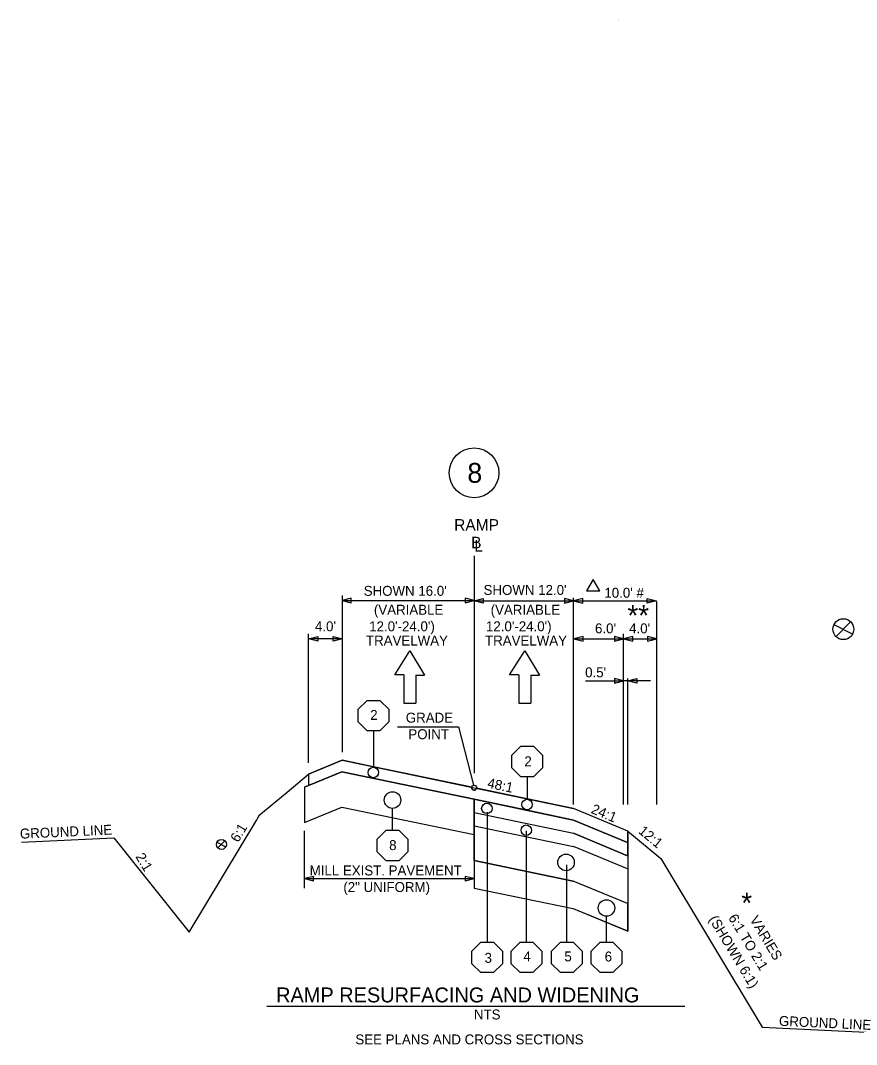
# Model space of a CAD drawing. Extents: x 5017 to 5774, y 4942 to 5266.
# Drawn here: x 5028.4 to 5129.3, y 5142.5 to 5266.1 of the extents above; entities that cross this region are included whole.
import ezdxf

# ---------------------------------------------------------------- set-up
doc = ezdxf.new("R2010")
doc.units = 0
for name, color, linetype in [('Level 2', 7, 'Continuous'), ('Level 20', 7, 'Continuous'), ('Level 25', 7, 'Continuous'), ('RD_DDB_EX_Tx', 7, 'Continuous'), ('RD_QTY_Intermediate', 7, 'Continuous'), ('RD_QTY_Surf_Course', 7, 'Continuous'), ('RD_SHT_Typical', 7, 'Continuous'), ('RD_TX_TypSect', 7, 'Continuous'), ('RD_XS_ExGround', 7, 'Continuous'), ('RD_XS_ExPaveRet', 7, 'Continuous'), ('typical_on', 7, 'Continuous')]:
    doc.layers.add(name, color=color, linetype=linetype)

msp = doc.modelspace()

# ---------------------------------------------------------------- linework, layer by layer
at = {"layer": 'Level 2'}
for p, q in [((5100.63, 5266.14), (5100.63, 5266.14)), ((5100.63, 5266.08), (5100.63, 5266.08))]:
    msp.add_line(p, q, dxfattribs=at)
at = {"layer": 'Level 20'}
for p, q in [((5073.55, 5187.12), (5075.37, 5190.03)), ((5075.37, 5190.03), (5077.16, 5187.11)), ((5087.43, 5187.12), (5089.25, 5190.03)), ((5089.25, 5190.03), (5091.04, 5187.11)), ((5074.64, 5187.12), (5073.55, 5187.12)), ((5074.64, 5187.12), (5074.64, 5183.72)), ((5076.1, 5187.11), (5077.16, 5187.11)), ((5076.1, 5187.11), (5076.1, 5183.71)), ((5088.52, 5187.12), (5087.43, 5187.12)), ((5088.52, 5187.12), (5088.52, 5183.72)), ((5089.98, 5187.11), (5091.04, 5187.11)), ((5089.98, 5187.11), (5089.98, 5183.71)), ((5074.64, 5183.72), (5076.1, 5183.71)), ((5088.52, 5183.72), (5089.98, 5183.71))]:
    msp.add_line(p, q, dxfattribs=at)
at = {"layer": 'Level 25'}
msp.add_lwpolyline([(5073.9, 5180.87), (5081.26, 5180.87), (5083.07, 5173.79)], dxfattribs=at)
msp.add_circle((5083.13, 5211.52), 3, dxfattribs=at)
at = {"layer": 'RD_DDB_EX_Tx'}
for p, q in [((5095.12, 5162.23), (5083.15, 5164.73)), ((5101.66, 5159.51), (5095.12, 5162.23)), ((5083.15, 5161.39), (5095.12, 5158.9)), ((5095.12, 5158.9), (5101.69, 5156.17)), ((5101.69, 5156.17), (5101.69, 5159.51))]:
    msp.add_line(p, q, dxfattribs=at)
for points in [[(5083.15, 5164.73), (5083.15, 5162.52), (5083.15, 5161.39)], [(5101.69, 5159.51), (5101.66, 5159.51)]]:
    msp.add_lwpolyline(points, dxfattribs=at)
msp.add_circle((5099.12, 5158.98), 1, dxfattribs=at)
at = {"layer": 'RD_QTY_Intermediate'}
for p, q in [((5083.15, 5172.1), (5083.15, 5170.51)), ((5083.15, 5170.51), (5095.15, 5168.01)), ((5101.67, 5166.89), (5095.15, 5169.6)), ((5095.15, 5168.01), (5101.67, 5165.29)), ((5101.69, 5165.29), (5101.69, 5166.89))]:
    msp.add_line(p, q, dxfattribs=at)
for points in [[(5095.15, 5169.6), (5089.51, 5170.78), (5083.15, 5172.1)], [(5101.69, 5166.89), (5101.67, 5166.89)], [(5101.67, 5165.29), (5101.69, 5165.29)]]:
    msp.add_lwpolyline(points, dxfattribs=at)
at = {"layer": 'RD_QTY_Surf_Course'}
for p, q in [((5067.21, 5176.82), (5063.16, 5175.13)), ((5070.99, 5176.03), (5067.21, 5176.82)), ((5070.99, 5175.97), (5070.99, 5176.03)), ((5082.85, 5173.56), (5071.01, 5176.03)), ((5063.16, 5173.76), (5067.18, 5175.43)), ((5063.16, 5175.13), (5063.16, 5173.76)), ((5067.18, 5175.43), (5083.15, 5172.1)), ((5089.55, 5172.17), (5083.44, 5173.44)), ((5083.15, 5172.1), (5095.15, 5169.6)), ((5089.55, 5172.1), (5089.55, 5172.17)), ((5095.15, 5171), (5089.56, 5172.16)), ((5101.69, 5168.27), (5095.15, 5171)), ((5095.15, 5169.6), (5101.67, 5166.89)), ((5101.69, 5166.89), (5101.69, 5168.27))]:
    msp.add_line(p, q, dxfattribs=at)
for points in [[(5071.01, 5176.03), (5070.99, 5175.97)], [(5089.56, 5172.16), (5089.55, 5172.1)], [(5101.67, 5166.89), (5101.69, 5166.89)]]:
    msp.add_lwpolyline(points, dxfattribs=at)
for centre in [(5070.97, 5175.34), (5089.54, 5171.47)]:
    msp.add_circle(centre, 0.63, dxfattribs=at)
msp.add_arc((5083.15, 5173.5), 0.3, 168.2319, 348.2319, dxfattribs=at)
at = {"layer": 'RD_SHT_Typical'}
for p, q in [((5063.16, 5175.13), (5067.21, 5176.82)), ((5062.66, 5173.55), (5067.18, 5175.43)), ((5063.16, 5173.76), (5067.18, 5175.43)), ((5063.16, 5175.13), (5063.16, 5173.76)), ((5062.66, 5173.55), (5062.66, 5169.29)), ((5083.15, 5172.1), (5083.15, 5170.73)), ((5062.66, 5169.29), (5067.18, 5171.17)), ((5083.15, 5170.73), (5083.15, 5167.84)), ((5101.69, 5168.27), (5095.15, 5171)), ((5101.67, 5166.89), (5095.15, 5169.6)), ((5083.15, 5164.73), (5083.15, 5168.91)), ((5101.69, 5168.27), (5105.69, 5164.94)), ((5101.69, 5168.27), (5101.69, 5156.17)), ((5101.67, 5165.29), (5095.15, 5168.01)), ((5101.67, 5163.69), (5095.15, 5166.41)), ((5105.69, 5164.94), (5117.91, 5144.57)), ((5101.66, 5159.51), (5095.12, 5162.23)), ((5101.69, 5156.17), (5095.15, 5158.89))]:
    msp.add_line(p, q, dxfattribs=at)
for points in [[(5067.21, 5176.82), (5083.15, 5173.5)], [(5067.18, 5175.43), (5083.15, 5172.1)], [(5067.18, 5175.43), (5083.15, 5172.1)], [(5083.15, 5173.5), (5095.15, 5171)], [(5083.15, 5172.1), (5095.15, 5169.6)], [(5067.18, 5171.17), (5083.15, 5167.84)], [(5083.15, 5170.51), (5095.15, 5168.01)], [(5083.15, 5168.91), (5095.15, 5166.41)], [(5083.15, 5164.73), (5095.12, 5162.23)], [(5083.15, 5161.39), (5095.12, 5158.9)]]:
    msp.add_lwpolyline(points, dxfattribs=at)
at = {"layer": 'RD_TX_TypSect'}
for p, q in [((5083.15, 5201.5), (5083.15, 5175.26)), ((5067.21, 5196.69), (5067.21, 5177.8)), ((5067.21, 5196.1), (5083.15, 5196.1)), ((5083.15, 5196.07), (5095.15, 5196.07)), ((5095.15, 5171.49), (5095.15, 5196.42)), ((5095.15, 5196.07), (5105.15, 5196.07)), ((5105.19, 5171.49), (5105.19, 5196)), ((5126.59, 5193.21), (5128.86, 5192.06)), ((5126.85, 5191.75), (5128.6, 5193.53)), ((5063.16, 5176.49), (5063.16, 5192.1)), ((5101.19, 5171.49), (5101.19, 5192.1)), ((5067.21, 5191.48), (5063.16, 5191.48)), ((5095.19, 5191.48), (5101.19, 5191.48)), ((5101.19, 5191.48), (5105.19, 5191.48)), ((5096.6, 5186.4), (5101.19, 5186.4)), ((5104.45, 5186.4), (5101.19, 5186.4)), ((5101.69, 5171.49), (5101.69, 5186.68)), ((5070.99, 5180.36), (5070.99, 5175.97)), ((5089.55, 5174.82), (5089.55, 5172.1)), ((5083.15, 5172.1), (5083.15, 5161.39)), ((5073.29, 5168.38), (5073.29, 5171.01)), ((5084.74, 5154.87), (5084.74, 5170.53)), ((5062.66, 5161.39), (5062.66, 5168.28)), ((5089.46, 5154.87), (5089.46, 5168.29)), ((5052.21, 5166.23), (5053.03, 5167.07)), ((5052.08, 5166.92), (5053.16, 5166.37)), ((5094.34, 5154.87), (5094.34, 5164.2)), ((5099.13, 5154.86), (5099.13, 5157.98)), ((5058.09, 5147.13), (5108.58, 5147.13))]:
    msp.add_line(p, q, dxfattribs=at)
for points in [[(5097.53, 5198.65), (5096.73, 5197.27), (5098.33, 5197.27)], [(5068.31, 5195.83), (5068.31, 5196.38), (5067.21, 5196.1)], [(5082.05, 5196.38), (5082.05, 5195.83), (5083.15, 5196.1)], [(5084.25, 5196.35), (5084.25, 5195.8), (5083.15, 5196.07)], [(5094.05, 5196.35), (5094.05, 5195.8), (5095.15, 5196.07)], [(5096.26, 5195.8), (5096.26, 5196.35), (5095.15, 5196.07)], [(5104.05, 5195.8), (5104.05, 5196.35), (5105.15, 5196.07)], [(5064.26, 5191.75), (5064.26, 5191.2), (5063.16, 5191.48)], [(5066.11, 5191.2), (5066.11, 5191.75), (5067.21, 5191.48)], [(5096.29, 5191.2), (5096.29, 5191.75), (5095.19, 5191.48)], [(5100.09, 5191.75), (5100.09, 5191.2), (5101.19, 5191.48)], [(5102.29, 5191.2), (5102.29, 5191.75), (5101.19, 5191.48)], [(5104.09, 5191.75), (5104.09, 5191.2), (5105.19, 5191.48)], [(5100.09, 5186.68), (5100.09, 5186.13), (5101.19, 5186.4)], [(5102.79, 5186.68), (5102.79, 5186.13), (5101.69, 5186.4)], [(5063.76, 5162.25), (5063.76, 5162.8), (5062.66, 5162.52)], [(5082.05, 5162.8), (5082.05, 5162.25), (5083.15, 5162.52)]]:
    msp.add_lwpolyline(points, close=True, dxfattribs=at)
for centre, radius in [((5127.73, 5192.64), 1.26), ((5070.97, 5175.34), 0.63), ((5083.15, 5173.5), 0.3), ((5073.29, 5172.01), 1), ((5089.54, 5171.47), 0.63), ((5084.68, 5171), 0.63), ((5089.44, 5168.37), 0.63), ((5052.63, 5166.65), 0.6), ((5094.24, 5164.48), 1), ((5099.12, 5158.98), 1)]:
    msp.add_circle(centre, radius, dxfattribs=at)
at = {"layer": 'RD_XS_ExGround'}
for p, q in [((5060.55, 5172.95), (5063.16, 5175.13)), ((5057.16, 5170.13), (5060.55, 5172.95)), ((5048.72, 5156.07), (5056.89, 5169.64)), ((5057.16, 5170.13), (5056.89, 5169.64)), ((5028.5, 5166.92), (5039.64, 5167.43)), ((5039.64, 5167.43), (5048.72, 5156.07)), ((5062.66, 5162.52), (5083.15, 5162.52)), ((5117.91, 5144.57), (5132.19, 5143.92))]:
    msp.add_line(p, q, dxfattribs=at)
at = {"layer": 'RD_XS_ExPaveRet'}
for p, q in [((5083.15, 5172.1), (5067.18, 5175.43)), ((5062.66, 5173.55), (5062.66, 5169.29)), ((5083.15, 5171.88), (5083.15, 5172.1)), ((5062.66, 5169.29), (5067.18, 5171.17)), ((5067.18, 5171.17), (5083.15, 5167.84))]:
    msp.add_line(p, q, dxfattribs=at)
for points in [[(5067.18, 5175.43), (5063.16, 5173.76), (5062.66, 5173.55)], [(5083.15, 5167.84), (5083.15, 5170.29), (5083.15, 5171.88)]]:
    msp.add_lwpolyline(points, dxfattribs=at)
at = {"layer": 'typical_on'}
for points in [[(5072.84, 5182.97), (5072.84, 5181.44), (5071.76, 5180.36), (5070.23, 5180.36), (5069.15, 5181.44), (5069.15, 5182.97), (5070.23, 5184.05), (5071.76, 5184.05)], [(5091.39, 5177.43), (5091.39, 5175.9), (5090.31, 5174.82), (5088.78, 5174.82), (5087.7, 5175.9), (5087.7, 5177.43), (5088.78, 5178.52), (5090.31, 5178.52)], [(5075.14, 5167.3), (5075.14, 5165.77), (5074.06, 5164.69), (5072.53, 5164.69), (5071.45, 5165.77), (5071.45, 5167.3), (5072.53, 5168.38), (5074.06, 5168.38)], [(5086.58, 5153.78), (5086.58, 5152.25), (5085.5, 5151.17), (5083.97, 5151.17), (5082.88, 5152.25), (5082.88, 5153.78), (5083.97, 5154.86), (5085.5, 5154.86)], [(5091.3, 5153.78), (5091.3, 5152.25), (5090.22, 5151.17), (5088.69, 5151.17), (5087.6, 5152.25), (5087.6, 5153.78), (5088.69, 5154.86), (5090.22, 5154.86)], [(5096.18, 5153.78), (5096.18, 5152.25), (5095.1, 5151.17), (5093.57, 5151.17), (5092.49, 5152.25), (5092.49, 5153.78), (5093.57, 5154.86), (5095.1, 5154.86)], [(5100.97, 5153.78), (5100.97, 5152.25), (5099.89, 5151.17), (5098.36, 5151.17), (5097.27, 5152.25), (5097.27, 5153.78), (5098.36, 5154.86), (5099.89, 5154.86)]]:
    msp.add_lwpolyline(points, close=True, dxfattribs=at)

# ---------------------------------------------------------------- texts
at = {"layer": 'Level 25'}
for s, height, p in [('8', 2.4, (5082.33, 5210.32)), ('RAMP', 1.4, (5080.73, 5204.53)), ('B ', 1.4, (5082.78, 5202.4)), ('GRADE', 1.2, (5074.89, 5181.36)), ('POINT', 1.2, (5075.2, 5179.36))]:
    msp.add_text(s, height=height, dxfattribs=at).set_placement(p)
at = {"layer": 'RD_TX_TypSect'}
for s, height, p in [('L', 1.4, (5083.17, 5202.01)), ("SHOWN 12.0'", 1.2, (5084.28, 5196.78)), ("SHOWN 16.0'", 1.2, (5069.81, 5196.67)), ("10.0' #", 1.2, (5098.87, 5196.44)), ('(VARIABLE', 1.2, (5071.04, 5194.39)), ('(VARIABLE', 1.2, (5085.14, 5194.39)), ('**', 2.5, (5101.66, 5193.05)), ("4.0'", 1.2, (5063.92, 5192.39)), ("12.0'-24.0')", 1.2, (5070.47, 5192.39)), ("12.0'-24.0')", 1.2, (5084.57, 5192.39)), ("6.0'", 1.2, (5097.74, 5192.14)), ("4.0'", 1.2, (5101.86, 5192.14)), ('TRAVELWAY', 1.2, (5070.08, 5190.67)), ('TRAVELWAY', 1.2, (5084.46, 5190.67)), ("0.5'", 1.2, (5096.55, 5186.83)), ('2', 1.2, (5070.59, 5181.69)), ('2', 1.2, (5089.21, 5176.09)), ('8', 1.2, (5072.88, 5165.97)), ('MILL EXIST. PAVEMENT', 1.2, (5063.28, 5162.91)), ('(2" UNIFORM)', 1.2, (5067.35, 5160.91)), ('*', 2.5, (5115.41, 5158.34)), ('3', 1.2, (5084.4, 5152.36)), ('4', 1.2, (5089.09, 5152.53)), ('5', 1.2, (5094.04, 5152.53)), ('6', 1.2, (5098.91, 5152.52)), ('RAMP RESURFACING AND WIDENING', 1.8, (5059.23, 5147.58)), ('NTS', 1.2, (5083.12, 5145.52)), ('SEE PLANS AND CROSS SECTIONS', 1.2, (5068.8, 5142.51))]:
    msp.add_text(s, height=height, dxfattribs=at).set_placement(p)
for s, rotation, p in [('48:1', 348.2317, (5084.66, 5173.52)), ('24:1', 337.3801, (5097.17, 5170.48)), ('GROUND LINE', 2.6095, (5028.32, 5167.34)), ('6:1', 59.0362, (5054.65, 5166.81)), ('12:1', 320.1939, (5102.89, 5168.11)), ('2:1', 300.9638, (5042.21, 5165.18)), ('(SHOWN 6:1)', 300.9638, (5111.44, 5157.64)), ('6:1 TO 2:1', 300.9638, (5113.79, 5157.8)), ('VARIES', 300.9638, (5116.37, 5157.59)), ('GROUND LINE', 357.3905, (5119.93, 5144.76))]:
    msp.add_text(s, height=1.2, rotation=rotation, dxfattribs=at).set_placement(p)

doc.saveas('drawing.dxf')
